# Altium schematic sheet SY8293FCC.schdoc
size 127 x 101 mm
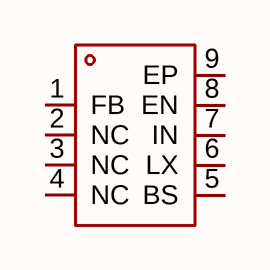
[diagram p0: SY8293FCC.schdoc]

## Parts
U?  sy8293fcc  [SO-8_L4.9-W3.9-P1.27-LS6.0-BL-EP]  (value not drawn)

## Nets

Not connected (* = marked no-connect by the designer): U? 1(FB) 2(NC) 3(NC) 4(NC) 5(BS) 6(LX) 7(IN) 8(EN) 9(EP)

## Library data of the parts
U? = sy8293fcc: 功能类型:降压型;工作电压:5V~40V;输出电压:-;输出电流:2.5A;输出类型:可调;; Manufacturer: Silergy(矽力杰); AddInBom: yes; ModelId: 756fba4e187a48c69a2c935cd5c4465b; ModelName: SO-8_L4.9-W3.9-H1.5-LS5.9-P1.27; ModelTransform: 240.39054,192.913,0,270,0,0,0.004,-0.002,0; Function: 降压型; Voltage - Supply: 5V~40V; Output Current: 2.5A; Frequency - Switching: 800kHz; Synchronous Rectifier: 否; Number of Outputs: 1; Topology: 降压式; Quiescent Current: 160uA; Switch tube (built-in/external): 内置; Output Type: 可调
